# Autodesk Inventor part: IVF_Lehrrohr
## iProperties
Created: 2009-01
Part Number: IVF_Lehrrohr
Document SubType Name: Modeling
Designer: USER1
Density: 1 g/cm^3
Mass: 309.938 g
Surface Area: 6200.19 cm^2
Volume: 309.938 cm^3
Author: USER1
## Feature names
1. Extrusion1
2. Shell1
3. Extrusion4
4. Extrusion7
5. Extrusion6
6. Extrusion9
7. Extrusion10
8. Wandstärke4
